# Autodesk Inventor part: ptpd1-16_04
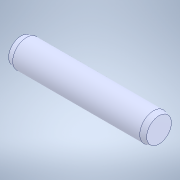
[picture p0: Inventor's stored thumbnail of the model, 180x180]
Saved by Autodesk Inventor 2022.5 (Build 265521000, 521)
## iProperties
Created: 2023-04
Part Number: ptpd1-16_04
Material: Generic
Document SubType Name: Modeling
Designer: ImaoCorp
Density: 1 g/cm^3
Appearance: Default
Author: ImaoCorp
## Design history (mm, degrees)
feature "ptpd1-16_04"
node "ソリッド1"
